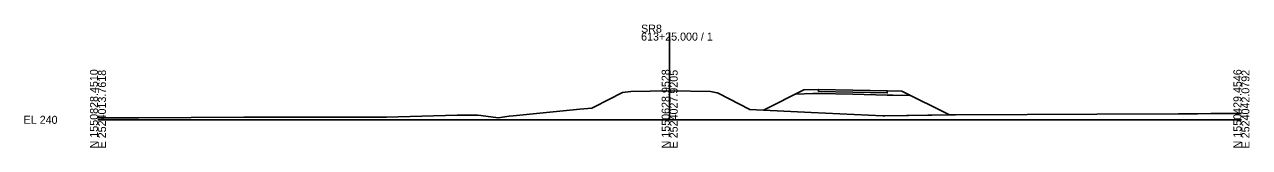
# Model space of a CAD drawing. Extents: x -26 to 2803, y -10 to 19537.
# Drawn here: x 2374.3 to 2802.8, y -9.7 to 33.4 of the extents above; entities that cross this region are included whole.
import ezdxf

# ---------------------------------------------------------------- set-up
doc = ezdxf.new("R2010")
doc.units = 0
for name, color, linetype in [('XS_CELL', 7, 'Continuous'), ('XS_M_MULTI', 7, 'Continuous'), ('XS_M_SHAPES_EARTHWORK', 7, 'Continuous'), ('XS_P_FINISHED_GRADE', 7, 'Continuous'), ('XS_P_SUBGRADE_GRANULAR', 7, 'Continuous'), ('XS_P_SUBGRADE_PAVEMENT', 7, 'Continuous'), ('XS_X_GROUND', 7, 'Continuous')]:
    doc.layers.add(name, color=color, linetype=linetype)

msp = doc.modelspace()

# ---------------------------------------------------------------- linework, layer by layer
at = {"layer": 'XS_CELL'}
for p, q in [((2600, 0), (2600, 30.52)), ((2400, 0), (2600, 0)), ((2600, 0), (2800, 0))]:
    msp.add_line(p, q, dxfattribs=at)
at = {"layer": 'XS_M_MULTI'}
for p, q in [((2632.77, 3.41), (2646.99, 10.46)), ((2646.99, 10.46), (2652.03, 10.66)), ((2652.03, 10.66), (2664.12, 10.42)), ((2664.12, 10.42), (2676.21, 10.18)), ((2676.21, 10.18), (2681.25, 9.98)), ((2681.25, 9.98), (2697.94, 1.7))]:
    msp.add_line(p, q, dxfattribs=at)
for points in [[(2400, 0.69), (2414.24, 0.74), (2450.98, 0.87), (2455.22, 0.88), (2478.22, 0.92), (2497.45, 0.96), (2500.98, 0.96), (2525.61, 1.63), (2526.81, 1.66), (2532.79, 1.57), (2533.89, 1.56), (2540.02, 0.71), (2543.9, 1.24), (2545.24, 1.43), (2568.56, 3.69), (2572.77, 4.1), (2573.42, 4.43), (2583.48, 9.51), (2586.38, 9.9), (2600, 10.17), (2600.43, 10.17), (2614.23, 9.92), (2616.59, 9.5), (2616.98, 9.29), (2628, 3.65), (2632.77, 3.41)], [(2697.94, 1.7), (2700.02, 1.73), (2725.06, 1.88), (2749.46, 2), (2777.96, 2.13), (2780.92, 2.14), (2784.6, 2.15), (2789.32, 2.17), (2795.61, 2.19), (2800, 2.21)]]:
    msp.add_lwpolyline(points, dxfattribs=at)
at = {"layer": 'XS_M_SHAPES_EARTHWORK'}
for points in [[(2676.12, 10.18), (2676.21, 10.18), (2681.25, 9.98), (2697.94, 1.7), (2675.25, 1.35), (2674.6, 1.34), (2649.51, 2.58), (2632.77, 3.41), (2646.99, 10.46), (2652.03, 10.66), (2652.12, 10.66), (2652.12, 9.91), (2664.12, 9.67), (2676.12, 9.43)], [(2652.12, 10.66), (2664.12, 10.42), (2676.12, 10.18), (2676.12, 9.43), (2664.12, 9.67), (2652.12, 9.91)]]:
    msp.add_lwpolyline(points, close=True, dxfattribs=at)
at = {"layer": 'XS_P_FINISHED_GRADE'}
for p, q in [((2646.99, 10.46), (2632.77, 3.41)), ((2652.03, 10.66), (2646.99, 10.46)), ((2652.03, 10.66), (2664.12, 10.42)), ((2664.12, 10.42), (2676.21, 10.18)), ((2676.21, 10.18), (2681.25, 9.98)), ((2681.25, 9.98), (2697.94, 1.7))]:
    msp.add_line(p, q, dxfattribs=at)
at = {"layer": 'XS_P_SUBGRADE_GRANULAR'}
for p, q in [((2650.12, 9.2), (2644.12, 8.96)), ((2652.12, 9.16), (2650.12, 9.2)), ((2652.12, 9.16), (2664.12, 8.92)), ((2664.12, 8.92), (2676.12, 8.68)), ((2676.12, 8.68), (2678.12, 8.64)), ((2678.12, 8.64), (2684.04, 8.52))]:
    msp.add_line(p, q, dxfattribs=at)
at = {"layer": 'XS_P_SUBGRADE_PAVEMENT'}
for p, q in [((2652.12, 9.91), (2652.12, 10.66)), ((2652.12, 9.91), (2664.12, 9.67)), ((2664.12, 9.67), (2676.12, 9.43)), ((2676.12, 9.43), (2676.12, 10.18))]:
    msp.add_line(p, q, dxfattribs=at)
at = {"layer": 'XS_X_GROUND'}
msp.add_lwpolyline([(2400, 0.69), (2414.24, 0.74), (2450.98, 0.87), (2455.22, 0.88), (2478.22, 0.92), (2497.45, 0.96), (2500.98, 0.96), (2525.61, 1.63), (2526.81, 1.66), (2532.79, 1.57), (2533.89, 1.56), (2540.02, 0.71), (2543.9, 1.24), (2545.24, 1.43), (2568.56, 3.69), (2572.77, 4.1), (2573.42, 4.43), (2583.48, 9.51), (2586.38, 9.9), (2600, 10.17), (2600.43, 10.17), (2614.23, 9.92), (2616.59, 9.5), (2616.98, 9.29), (2628, 3.65), (2649.51, 2.58), (2674.6, 1.34), (2675.25, 1.35), (2700.02, 1.73), (2725.06, 1.88), (2749.46, 2), (2777.96, 2.13), (2780.92, 2.14), (2784.6, 2.15), (2789.32, 2.17), (2795.61, 2.19), (2800, 2.21)], dxfattribs=at)

# ---------------------------------------------------------------- texts
at = {"layer": 'XS_CELL'}
for s, p in [('SR8', (2590, 30.52)), ('613+25.000 / 1', (2590, 27.72)), ('EL 240', (2374, -1.4))]:
    msp.add_text(s, height=2.8, dxfattribs=at).set_placement(p)
for s, p in [('N 1550828.4510', (2400, -10)), ('E 2524013.7618', (2402.8, -10)), ('N 1550628.9528', (2600, -10)), ('E 2524027.9205', (2602.8, -10)), ('N 1550429.4546', (2800, -10)), ('E 2524042.0792', (2802.8, -10))]:
    msp.add_text(s, height=2.8, rotation=90, dxfattribs=at).set_placement(p)

doc.saveas('drawing.dxf')
